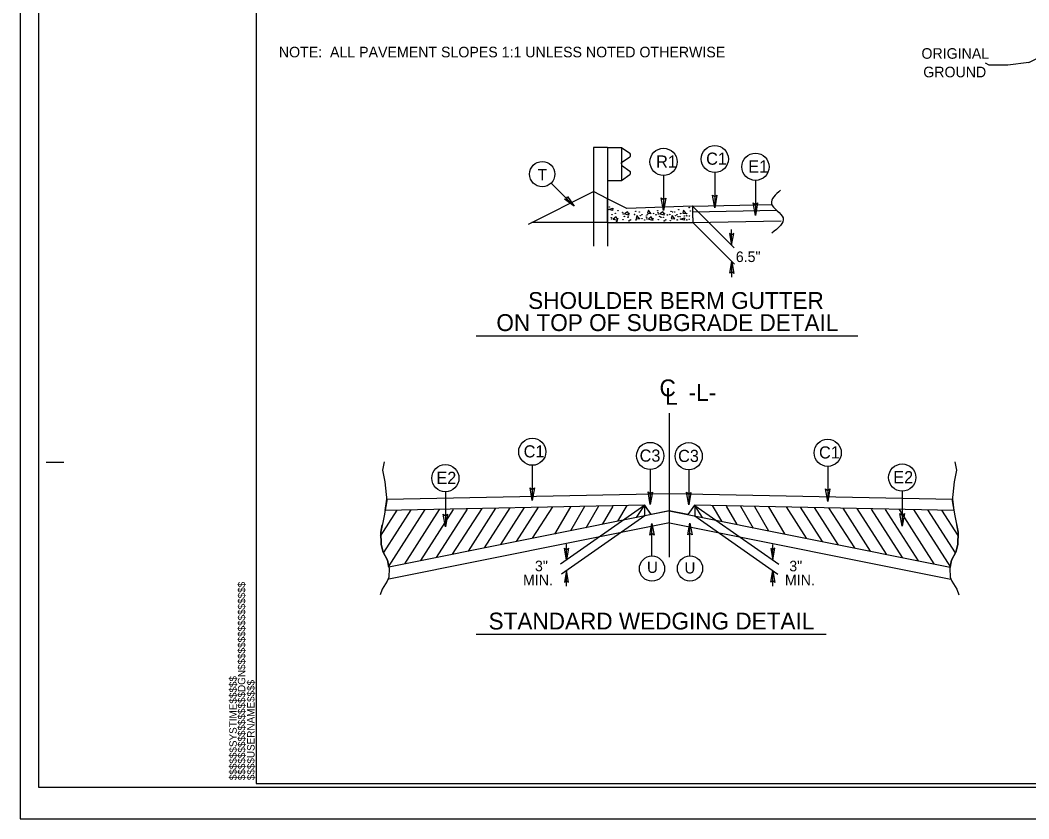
# Model space of a CAD drawing. Extents: x 60664 to 60833, y 51234 to 51344.
# Drawn here: x 60664.4 to 60735.8, y 51234.4 to 51291 of the extents above; entities that cross this region are included whole.
import ezdxf

# ---------------------------------------------------------------- set-up
doc = ezdxf.new("R2010")
doc.units = 0
for name, color, linetype in [('Prop Dimension', 7, 'Continuous'), ('Prop Dimension Text', 7, 'Continuous'), ('Prop Pavement Schedule Description CELL', 7, 'Continuous'), ('Sheet Cutting Line CELL', 7, 'Continuous'), ('Sheet Plot Border Inside CELL', 7, 'Continuous'), ('Sheet Plot Border Outside CELL', 7, 'Continuous'), ('Sheet Typical CELL', 7, 'Continuous'), ('Typical Curb CELL', 7, 'Continuous'), ('Typical Detail Wedge2 CELL', 7, 'Continuous'), ('Typical Guardrail CELL', 7, 'Continuous'), ('Typical ID Circle CELL', 7, 'Continuous'), ('Typical Pavement Slope CELL', 7, 'Continuous'), ('Typical Slope Point Local CELL', 7, 'Continuous'), ('Typical Terminator CELL', 7, 'Continuous'), ('Typical Text ID Circle CELL', 7, 'Continuous'), ('Typical Text Label CELL', 7, 'Continuous')]:
    doc.layers.add(name, color=color, linetype=linetype)

msp = doc.modelspace()

# ---------------------------------------------------------------- linework, layer by layer
at = {"layer": 'Prop Dimension'}
for p, q in [((60712.013, 51277.804), (60714.961, 51274.856)), ((60712.035, 51276.638), (60714.979, 51273.693)), ((60714.784, 51275.033), (60714.784, 51276.143)), ((60714.803, 51272.76), (60714.803, 51273.87)), ((60710.386, 51252.944), (60710.386, 51263.145)), ((60708.629, 51256.614), (60702.677, 51252.445)), ((60712.169, 51256.606), (60718.121, 51252.437)), ((60708.629, 51255.865), (60702.741, 51251.743)), ((60712.169, 51255.857), (60718.057, 51251.735)), ((60703.101, 51252.742), (60703.101, 51253.852)), ((60717.697, 51252.734), (60717.697, 51253.844)), ((60703.101, 51250.885), (60703.101, 51251.995)), ((60717.697, 51250.877), (60717.697, 51251.987))]:
    msp.add_line(p, q, dxfattribs=at)
msp.add_spline([(60718.248, 51278.919), (60717.605, 51277.983), (60718.424, 51276.959), (60717.634, 51275.876)], degree=3, dxfattribs=at)
at = {"layer": 'Sheet Cutting Line CELL'}
for p, q in [((60664.421, 51344.408), (60664.421, 51234.408)), ((60664.421, 51234.408), (60832.821, 51234.408))]:
    msp.add_line(p, q, dxfattribs=at)
at = {"layer": 'Sheet Plot Border Inside CELL'}
msp.add_lwpolyline([(60832.371, 51342.163), (60665.721, 51342.163), (60665.721, 51236.653), (60832.371, 51236.653)], close=True, dxfattribs=at)
at = {"layer": 'Sheet Plot Border Outside CELL'}
msp.add_lwpolyline([(60832.821, 51344.408), (60664.421, 51344.408), (60664.421, 51234.408), (60832.821, 51234.408)], close=True, dxfattribs=at)
at = {"layer": 'Sheet Typical CELL'}
for p, q in [((60666.271, 51259.658), (60667.521, 51259.658)), ((60681.121, 51236.908), (60681.121, 51236.908)), ((60681.121, 51236.908), (60681.121, 51236.908)), ((60681.121, 51236.908), (60681.121, 51236.908)), ((60681.121, 51236.908), (60681.121, 51236.908)), ((60681.121, 51236.908), (60681.121, 51236.908)), ((60681.121, 51236.908), (60681.121, 51236.908))]:
    msp.add_line(p, q, dxfattribs=at)
msp.add_lwpolyline([(60831.121, 51341.908), (60681.121, 51341.908), (60681.121, 51236.908), (60831.121, 51236.908)], close=True, dxfattribs=at)
msp.add_lwpolyline([(60684.871, 51236.908), (60684.871, 51236.908)], dxfattribs=at)
at = {"layer": 'Typical Curb CELL'}
for p, q in [((60705.994, 51276.638), (60705.994, 51278.326)), ((60707.369, 51277.638), (60705.994, 51278.326)), ((60706.067, 51277.57), (60706.375, 51277.659)), ((60706.342, 51277.478), (60706.067, 51277.57)), ((60706.375, 51277.659), (60706.342, 51277.478)), ((60707.406, 51277.403), (60707.2, 51277.253)), ((60712.013, 51277.804), (60707.369, 51277.638)), ((60707.531, 51277.173), (60707.406, 51277.403)), ((60708.889, 51277.515), (60708.821, 51277.288)), ((60709.06, 51277.275), (60708.889, 51277.515)), ((60709.904, 51277.403), (60709.697, 51277.253)), ((60710.029, 51277.173), (60709.904, 51277.403)), ((60711.387, 51277.515), (60711.318, 51277.288)), ((60711.56, 51277.275), (60711.387, 51277.515)), ((60712.035, 51277.805), (60712.035, 51277.805)), ((60712.035, 51276.972), (60712.035, 51277.784)), ((60705.994, 51276.638), (60712.035, 51276.638)), ((60706.601, 51277.032), (60706.395, 51276.882)), ((60706.395, 51276.882), (60706.726, 51276.803)), ((60706.726, 51276.803), (60706.601, 51277.032)), ((60707.2, 51277.253), (60707.531, 51277.173)), ((60708.084, 51277.145), (60708.015, 51276.918)), ((60708.015, 51276.918), (60708.255, 51276.905)), ((60708.255, 51276.905), (60708.084, 51277.145)), ((60708.821, 51277.288), (60709.06, 51277.275)), ((60709.099, 51277.032), (60708.892, 51276.882)), ((60708.892, 51276.882), (60709.224, 51276.803)), ((60709.224, 51276.803), (60709.099, 51277.032)), ((60709.697, 51277.253), (60710.029, 51277.173)), ((60710.582, 51277.145), (60710.513, 51276.918)), ((60710.513, 51276.918), (60710.755, 51276.905)), ((60710.755, 51276.905), (60710.582, 51277.145)), ((60711.147, 51276.884), (60711.455, 51276.974)), ((60711.422, 51276.793), (60711.147, 51276.884)), ((60711.318, 51277.288), (60711.56, 51277.275)), ((60711.455, 51276.974), (60711.422, 51276.793))]:
    msp.add_line(p, q, dxfattribs=at)
for centre in [(60706.123, 51277.74), (60706.558, 51277.295), (60706.733, 51277.47), (60707.071, 51277.352), (60707.516, 51277.284), (60707.998, 51277.436), (60708.25, 51277.379), (60709.056, 51277.295), (60709.549, 51277.471), (60709.569, 51277.352), (60710.014, 51277.284), (60710.497, 51277.436), (60710.597, 51277.375), (60710.748, 51277.379), (60711.045, 51277.55), (60711.779, 51277.7), (60711.855, 51277.45), (60706.266, 51276.982), (60706.3, 51276.881), (60706.318, 51277.194), (60706.654, 51276.71), (60706.711, 51276.913), (60707.1, 51276.835), (60707.105, 51277.251), (60707.193, 51277.066), (60707.445, 51277.009), (60707.459, 51277.08), (60707.511, 51276.756), (60707.623, 51276.824), (60707.905, 51277.205), (60708.011, 51276.824), (60708.251, 51276.925), (60708.316, 51277.126), (60708.428, 51277.194), (60708.438, 51276.906), (60708.63, 51276.815), (60708.744, 51277.1), (60708.764, 51276.982), (60708.798, 51276.881), (60708.816, 51277.194), (60709.209, 51276.913), (60709.243, 51277.276), (60709.435, 51277.185), (60709.598, 51276.835), (60709.604, 51277.251), (60709.692, 51277.066), (60709.792, 51277.005), (60709.943, 51277.009), (60710.009, 51276.756), (60710.121, 51276.824), (60710.24, 51277.18), (60710.403, 51277.205), (60710.449, 51276.774), (60710.814, 51277.126), (60710.926, 51277.194), (60710.929, 51276.825), (60710.997, 51277.045), (60711.137, 51277.045), (60711.177, 51277.274), (60711.429, 51277.094), (60711.604, 51277.269), (60711.606, 51277.114), (60711.609, 51276.825), (60711.777, 51276.865), (60711.797, 51277.094)]:
    msp.add_circle(centre, 0.016, dxfattribs=at)
msp.add_arc((60712.014, 51277.784), 0.0208, 0, 92.04801, dxfattribs=at)
at = {"layer": 'Typical Detail Wedge2 CELL'}
for p, q in [((60690.365, 51257.051), (60710.385, 51257.45)), ((60690.365, 51257.051), (60710.385, 51257.45)), ((60710.385, 51257.45), (60730.407, 51257.051)), ((60710.388, 51257.45), (60730.407, 51257.051)), ((60690.251, 51256.246), (60690.365, 51257.051)), ((60708.629, 51256.614), (60690.251, 51256.246)), ((60708.629, 51256.614), (60690.251, 51256.246)), ((60707.368, 51256.597), (60706.715, 51255.478)), ((60708.06, 51255.758), (60708.604, 51256.606)), ((60708.604, 51256.606), (60708.604, 51255.857)), ((60709.079, 51255.954), (60708.629, 51256.614)), ((60709.079, 51255.954), (60708.629, 51256.592)), ((60712.157, 51256.614), (60711.692, 51255.954)), ((60712.157, 51256.614), (60711.692, 51255.954)), ((60712.127, 51256.599), (60712.156, 51256.597)), ((60730.522, 51256.246), (60712.157, 51256.614)), ((60730.522, 51256.246), (60712.157, 51256.614)), ((60712.712, 51255.758), (60712.169, 51256.606)), ((60712.169, 51256.606), (60712.169, 51255.857)), ((60713.404, 51256.597), (60714.057, 51255.478)), ((60730.407, 51257.051), (60730.522, 51256.246)), ((60730.407, 51257.051), (60730.522, 51256.246)), ((60710.415, 51256.22), (60690.516, 51252.239)), ((60703.379, 51256.508), (60702.241, 51254.559)), ((60704.378, 51256.529), (60703.37, 51254.8)), ((60705.367, 51256.548), (60704.463, 51254.999)), ((60706.363, 51256.546), (60705.614, 51255.263)), ((60710.356, 51256.22), (60709.079, 51255.954)), ((60710.356, 51256.22), (60709.079, 51255.954)), ((60710.356, 51256.22), (60730.257, 51252.239)), ((60711.692, 51255.954), (60710.356, 51256.22)), ((60711.692, 51255.954), (60710.356, 51256.22)), ((60714.408, 51256.546), (60715.158, 51255.263)), ((60715.405, 51256.548), (60716.309, 51254.999)), ((60716.394, 51256.529), (60717.402, 51254.8)), ((60717.394, 51256.508), (60718.515, 51254.587)), ((60710.378, 51255.363), (60690.509, 51251.389)), ((60710.393, 51255.363), (60730.309, 51251.379))]:
    msp.add_line(p, q, dxfattribs=at)
for points in [[(60690.179, 51259.693), (60690.072, 51259.106), (60690.233, 51258.273), (60690.374, 51256.923), (60690.179, 51255.857), (60689.949, 51254.703), (60689.967, 51253.832), (60690.108, 51253.283), (60690.429, 51252.731), (60690.535, 51252.128), (60690.517, 51251.524), (60690.41, 51251.239), (60690.038, 51250.671), (60689.913, 51250.28)], [(60730.592, 51259.693), (60730.699, 51259.106), (60730.539, 51258.273), (60730.397, 51256.923), (60730.592, 51255.857), (60730.823, 51254.703), (60730.806, 51253.832), (60730.663, 51253.283), (60730.343, 51252.731), (60730.238, 51252.128), (60730.254, 51251.524), (60730.361, 51251.239), (60730.734, 51250.671), (60730.858, 51250.28)], [(60689.927, 51254.428), (60691.106, 51256.269)], [(60690.158, 51253.267), (60692.094, 51256.289)], [(60690.495, 51252.247), (60693.097, 51256.309)], [(60691.648, 51252.465), (60694.107, 51256.305)], [(60692.774, 51252.691), (60695.103, 51256.325)], [(60693.893, 51252.914), (60696.09, 51256.344)], [(60695.031, 51253.142), (60697.114, 51256.392)], [(60696.15, 51253.366), (60698.102, 51256.412)], [(60697.278, 51253.591), (60699.098, 51256.432)], [(60698.439, 51253.824), (60700.124, 51256.454)], [(60699.566, 51254.049), (60701.12, 51256.474)], [(60700.694, 51254.275), (60702.116, 51256.494)], [(60720.088, 51254.273), (60718.665, 51256.494)], [(60721.215, 51254.048), (60719.66, 51256.474)], [(60722.334, 51253.824), (60720.648, 51256.454)], [(60723.495, 51253.591), (60721.675, 51256.432)], [(60724.623, 51253.366), (60722.671, 51256.412)], [(60725.741, 51253.142), (60723.658, 51256.392)], [(60726.878, 51252.915), (60724.681, 51256.344)], [(60728.006, 51252.689), (60725.677, 51256.324)], [(60729.124, 51252.465), (60726.665, 51256.305)], [(60730.294, 51252.231), (60727.682, 51256.309)], [(60730.635, 51253.234), (60728.677, 51256.289)], [(60730.818, 51254.469), (60729.665, 51256.269)], [(60690.515, 51252.239), (60690.429, 51252.731), (60690.108, 51253.283), (60689.967, 51253.832), (60689.949, 51254.703), (60690.056, 51255.238)], [(60730.257, 51252.239), (60730.343, 51252.731), (60730.663, 51253.283), (60730.806, 51253.832), (60730.823, 51254.703), (60730.716, 51255.238)]]:
    msp.add_lwpolyline(points, dxfattribs=at)
at = {"layer": 'Typical Guardrail CELL'}
for p, q in [((60705.994, 51281.943), (60704.999, 51281.943)), ((60704.999, 51281.943), (60704.999, 51276.638)), ((60705.994, 51281.943), (60705.994, 51276.972)), ((60705.994, 51281.943), (60706.989, 51281.943)), ((60706.989, 51281.943), (60706.989, 51279.623)), ((60706.989, 51281.943), (60707.567, 51281.537)), ((60706.989, 51280.877), (60707.567, 51281.282)), ((60706.989, 51280.783), (60706.989, 51280.877)), ((60706.989, 51280.783), (60706.989, 51280.69)), ((60706.989, 51280.69), (60707.567, 51280.284)), ((60705.994, 51279.623), (60706.989, 51279.623)), ((60706.989, 51279.623), (60707.567, 51280.029)), ((60705.994, 51276.638), (60704.999, 51276.638)), ((60704.999, 51276.638), (60704.999, 51274.955)), ((60705.994, 51276.972), (60705.994, 51274.955))]:
    msp.add_line(p, q, dxfattribs=at)
for centre, start, end in [((60707.479, 51281.41), 304.9888, 54.99703), ((60707.479, 51280.157), 304.9634, 54.9941)]:
    msp.add_arc(centre, 0.155, start, end, dxfattribs=at)
at = {"layer": 'Typical ID Circle CELL'}
for p, q in [((60713.592, 51280.173), (60713.592, 51277.687)), ((60709.963, 51279.968), (60709.963, 51277.482)), ((60716.469, 51279.622), (60716.469, 51277.137)), ((60700.673, 51259.444), (60700.673, 51256.959)), ((60709.022, 51259.146), (60709.022, 51256.661)), ((60711.746, 51259.124), (60711.746, 51256.639)), ((60721.583, 51259.371), (60721.583, 51256.885)), ((60694.519, 51257.57), (60694.519, 51255.085)), ((60726.859, 51257.617), (60726.859, 51255.132)), ((60709.145, 51253.022), (60709.145, 51255.333)), ((60711.835, 51253.032), (60711.835, 51255.343))]:
    msp.add_line(p, q, dxfattribs=at)
for centre, radius in [((60709.963, 51280.929), 0.962), ((60713.592, 51281.134), 0.962), ((60716.469, 51280.584), 0.962), ((60700.673, 51260.406), 0.962), ((60709.022, 51260.108), 0.962), ((60711.746, 51260.086), 0.962), ((60721.583, 51260.332), 0.962), ((60694.519, 51258.532), 0.962), ((60726.859, 51258.578), 0.962), ((60709.145, 51252.128), 0.894), ((60711.835, 51252.138), 0.894)]:
    msp.add_circle(centre, radius, dxfattribs=at)
at = {"layer": 'Typical Pavement Slope CELL'}
for p, q in [((60712.013, 51277.804), (60717.576, 51277.916)), ((60712.035, 51277.388), (60717.957, 51277.506)), ((60712.035, 51276.972), (60712.035, 51276.638)), ((60712.035, 51276.638), (60718.281, 51276.763))]:
    msp.add_line(p, q, dxfattribs=at)
at = {"layer": 'Typical Slope Point Local CELL'}
for p, q in [((60735.821, 51287.965), (60741.572, 51290.841)), ((60700.403, 51276.525), (60704.999, 51278.823)), ((60705.994, 51278.326), (60704.999, 51278.823)), ((60704.999, 51276.638), (60700.629, 51276.638))]:
    msp.add_line(p, q, dxfattribs=at)
msp.add_lwpolyline([(60735.821, 51287.965), (60734.327, 51287.779), (60733.954, 51287.779), (60733.393, 51287.779), (60733.019, 51287.779), (60732.754, 51287.911)], dxfattribs=at)
at = {"layer": 'Typical Terminator CELL'}
for points in [[(60710.116, 51278.373), (60709.963, 51277.482), (60709.804, 51278.378), (60709.963, 51278.264)], [(60713.746, 51278.578), (60713.592, 51277.687), (60713.434, 51278.583), (60713.592, 51278.469)], [(60716.622, 51278.027), (60716.469, 51277.137), (60716.31, 51278.032), (60716.469, 51277.918)], [(60714.642, 51275.861), (60714.784, 51275.033), (60714.932, 51275.866), (60714.784, 51275.76)], [(60714.66, 51273.042), (60714.803, 51273.87), (60714.95, 51273.037), (60714.803, 51273.143)], [(60700.827, 51257.85), (60700.673, 51256.959), (60700.515, 51257.854), (60700.673, 51257.741)], [(60709.175, 51257.551), (60709.022, 51256.661), (60708.864, 51257.556), (60709.022, 51257.442)], [(60711.899, 51257.529), (60711.746, 51256.639), (60711.587, 51257.534), (60711.746, 51257.42)], [(60721.736, 51257.776), (60721.583, 51256.885), (60721.425, 51257.781), (60721.583, 51257.667)], [(60694.672, 51255.975), (60694.519, 51255.085), (60694.36, 51255.98), (60694.519, 51255.867)], [(60727.012, 51256.022), (60726.859, 51255.132), (60726.7, 51256.027), (60726.859, 51255.913)], [(60709.002, 51254.505), (60709.145, 51255.333), (60709.292, 51254.5), (60709.145, 51254.606)], [(60711.692, 51254.515), (60711.835, 51255.343), (60711.982, 51254.511), (60711.835, 51254.617)], [(60703.244, 51253.57), (60703.101, 51252.742), (60702.954, 51253.574), (60703.101, 51253.469)], [(60717.554, 51253.562), (60717.697, 51252.734), (60717.844, 51253.567), (60717.697, 51253.461)], [(60703.244, 51251.167), (60703.101, 51251.995), (60702.954, 51251.162), (60703.101, 51251.268)], [(60717.554, 51251.159), (60717.697, 51251.987), (60717.844, 51251.154), (60717.697, 51251.26)]]:
    msp.add_lwpolyline(points, close=True, dxfattribs=at)
at = {"layer": 'Typical Text ID Circle CELL'}
msp.add_line((60702.007, 51279.434), (60703.642, 51277.799), dxfattribs=at)
msp.add_lwpolyline([(60703.157, 51278.486), (60703.642, 51277.799), (60702.949, 51278.284), (60703.128, 51278.313)], close=True, dxfattribs=at)
msp.add_circle((60701.375, 51280.066), 0.894, dxfattribs=at)
at = {"layer": 'Typical Text Label CELL'}
for p, q in [((60696.708, 51268.61), (60723.708, 51268.61)), ((60696.708, 51247.475), (60721.486, 51247.475))]:
    msp.add_line(p, q, dxfattribs=at)

# ---------------------------------------------------------------- texts
at = {"layer": 'Prop Dimension Text'}
for s, height, p in [('ORIGINAL ', 0.75, (60728.221, 51288.234)), ('GROUND', 0.75, (60728.348, 51286.921)), ('6.5"', 0.75, (60715.077, 51273.838)), ('C    ', 1.1936, (60709.678, 51264.328)), ('-L-', 1.1936, (60711.74, 51264.003)), ('L', 1.194, (60710.078, 51263.727)), ('3"', 0.75, (60700.862, 51251.942)), ('3"', 0.75, (60718.864, 51251.934)), ('MIN.', 0.75, (60700.016, 51250.955)), ('MIN.', 0.75, (60718.557, 51250.947))]:
    msp.add_text(s, height=height, dxfattribs=at).set_placement(p)
at = {"layer": 'Prop Pavement Schedule Description CELL'}
msp.add_text('NOTE:  ALL PAVEMENT SLOPES 1:1 UNLESS NOTED OTHERWISE', height=0.75, dxfattribs=at).set_placement((60682.731, 51288.334))
at = {"layer": 'Sheet Typical CELL'}
for s, p in [('$$$$$$$$$$$$$$$$DGN$$$$$$$$$$$$$$$$', (60680.356, 51237.144)), ('$$$$$$SYSTIME$$$$$', (60679.751, 51237.144)), ('$$$$USERNAME$$$$', (60681.013, 51237.145))]:
    msp.add_text(s, height=0.525, rotation=90, dxfattribs=at).set_placement(p)
at = {"layer": 'Typical Text ID Circle CELL'}
for s, height, p in [('C1', 0.8608, (60712.98, 51280.728)), ('R1', 0.8608, (60709.439, 51280.523)), ('E1', 0.8608, (60715.961, 51280.177)), ('T', 0.8, (60701.056, 51279.619)), ('C1', 0.8608, (60700.061, 51260)), ('C3', 0.8608, (60708.27, 51259.701)), ('C3', 0.8608, (60710.994, 51259.679)), ('C1', 0.8608, (60720.971, 51259.926)), ('E2', 0.8608, (60693.886, 51258.125)), ('E2', 0.8608, (60726.226, 51258.172)), ('U', 0.8, (60708.79, 51251.822)), ('U', 0.8, (60711.444, 51251.784))]:
    msp.add_text(s, height=height, dxfattribs=at).set_placement(p)
at = {"layer": 'Typical Text Label CELL'}
for s, p in [('SHOULDER BERM GUTTER ', (60700.379, 51270.517)), ('ON TOP OF SUBGRADE DETAIL ', (60698.13, 51268.952)), ('STANDARD WEDGING DETAIL', (60697.577, 51247.817))]:
    msp.add_text(s, height=1.1936, dxfattribs=at).set_placement(p)

doc.saveas('drawing.dxf')
